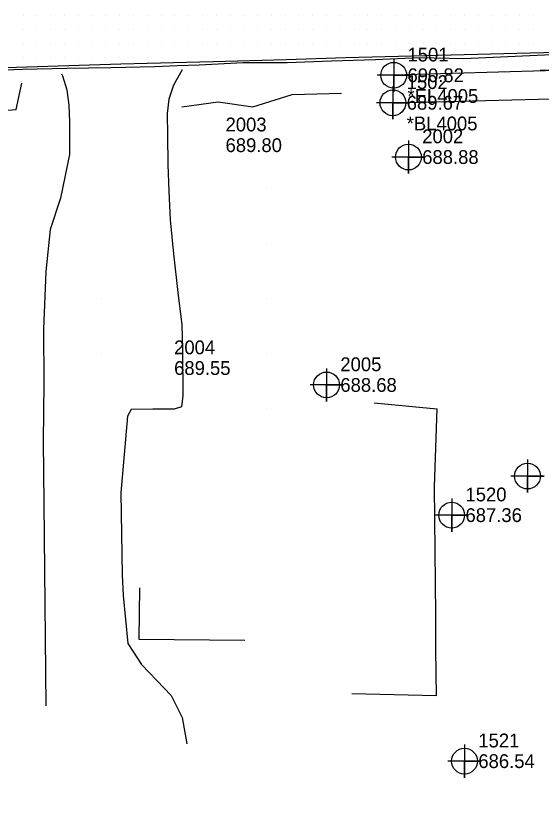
# Model space of a CAD drawing. Extents: x 1755643 to 1760494, y 736519 to 737621.
# Drawn here: x 1757879.9 to 1757975.2, y 736844.1 to 736986.2 of the extents above; entities that cross this region are included whole.
import ezdxf

# ---------------------------------------------------------------- set-up
doc = ezdxf.new("R2010")
doc.units = 0
for name, color, linetype in [('Exist Horizontal Alignment Curve and Spiral Data', 7, 'Continuous'), ('Exist Horizontal Alignment Direction Label', 7, 'Continuous'), ('Exist Railroads Standard Gauge', 7, 'Continuous'), ('Exist Roads EOT', 7, 'Continuous'), ('Old_Level_3', 7, 'Continuous'), ('Prop Corridor Linear Feature', 7, 'Continuous'), ('Prop EOT Dash', 7, 'Continuous'), ('Prop Lane Lines', 7, 'Continuous'), ('Prop Paint Stripe', 7, 'Continuous'), ('Prop Paved Shoulder', 7, 'Continuous'), ('Scratch_Level_1', 7, 'Continuous'), ('Scratch_Level_2', 7, 'Continuous'), ('Scratch_Level_5', 7, 'Continuous'), ('Scratch_Level_9', 7, 'Continuous')]:
    doc.layers.add(name, color=color, linetype=linetype)

msp = doc.modelspace()

# ---------------------------------------------------------------- linework, layer by layer
at = {"layer": 'Exist Horizontal Alignment Curve and Spiral Data'}
for points in [[(1757951.09, 736963.61), (1757951.09, 736957.61), (1757951.09, 736960.61), (1757954.09, 736960.61), (1757948.09, 736960.61)], [(1757936.25, 736922.27), (1757936.25, 736916.27), (1757936.25, 736919.27), (1757939.25, 736919.27), (1757933.25, 736919.27)], [(1757972.67, 736905.75), (1757972.67, 736899.75), (1757972.67, 736902.75), (1757975.67, 736902.75), (1757969.67, 736902.75)], [(1757958.93, 736898.66), (1757958.93, 736892.66), (1757958.93, 736895.66), (1757961.93, 736895.66), (1757955.93, 736895.66)], [(1757961.26, 736854.04), (1757961.26, 736848.04), (1757961.26, 736851.04), (1757964.26, 736851.04), (1757958.26, 736851.04)]]:
    msp.add_lwpolyline(points, dxfattribs=at)
for centre in [(1757951.09, 736960.61), (1757936.25, 736919.27), (1757972.67, 736902.75), (1757958.93, 736895.66), (1757961.26, 736851.04)]:
    msp.add_circle(centre, 2.34, dxfattribs=at)
at = {"layer": 'Exist Railroads Standard Gauge'}
for points in [[(1757888.22, 736975.69), (1757888.36, 736975.33), (1757889.19, 736972.8), (1757889.53, 736969.99), (1757889.65, 736966.99), (1757889.68, 736961.07), (1757888.01, 736953.18), (1757886.14, 736947.49), (1757885.38, 736939.87), (1757884.94, 736929.36), (1757884.98, 736919.6), (1757884.89, 736909.08), (1757884.99, 736897.85), (1757885.16, 736879.5), (1757885.39, 736861.05)], [(1757910.1, 736976.44), (1757908.52, 736973.63), (1757907.65, 736971.11), (1757907.38, 736968.52), (1757907.41, 736964.52), (1757907.5, 736959.27), (1757907.69, 736954.39), (1757907.92, 736949.25), (1757908.49, 736943.06), (1757909.29, 736936.07), (1757910.03, 736930.15), (1757910.12, 736925.65), (1757910.18, 736917.37), (1757909.95, 736915.28), (1757908.61, 736914.91), (1757904.76, 736914.88), (1757900.84, 736914.84), (1757900.16, 736913.63), (1757898.97, 736899.73), (1757899.21, 736884.83), (1757899.36, 736881.07), (1757900.24, 736872.37), (1757902.71, 736868.56), (1757905.48, 736865.69), (1757908.09, 736862.97), (1757910.08, 736858.98), (1757910.94, 736854.21)], [(1757876.09, 736968.9), (1757879.99, 736969.25), (1757881.01, 736973.98)], [(1757910.02, 736969.73), (1757916.63, 736970.65), (1757922.89, 736969.7), (1757930.01, 736971.93), (1757938.97, 736972.17)], [(1757944.85, 736916), (1757956.24, 736914.95), (1757955.76, 736900.8), (1757955.97, 736877.58), (1757956.02, 736871.3), (1757956.1, 736862.88), (1757940.85, 736863.23)], [(1757902.32, 736882.45), (1757902.22, 736873.18), (1757921.41, 736872.97)]]:
    msp.add_lwpolyline(points, dxfattribs=at)
at = {"layer": 'Prop Corridor Linear Feature'}
msp.add_lwpolyline([(1757909.25, 736977.13), (1757905.15, 736976.98), (1757897.16, 736976.76), (1757889.16, 736976.64)], dxfattribs=at)
at = {"layer": 'Prop Lane Lines'}
for points in [[(1757977.96, 736979.28), (1757977.96, 736973.28), (1757977.96, 736976.28), (1757980.96, 736976.28), (1757974.96, 736976.28)], [(1757948.42, 736978.44), (1757948.42, 736972.44), (1757948.42, 736975.44), (1757951.42, 736975.44), (1757945.42, 736975.44)], [(1757948.28, 736973.45), (1757948.28, 736967.45), (1757948.28, 736970.45), (1757951.28, 736970.45), (1757945.28, 736970.45)]]:
    msp.add_lwpolyline(points, dxfattribs=at)
for centre in [(1757948.42, 736975.44), (1757948.28, 736970.45)]:
    msp.add_circle(centre, 2.34, dxfattribs=at)
at = {"layer": 'Prop Paint Stripe'}
for p, q in [((1757925.38, 736954.98), (1757925.38, 736954.98)), ((1757925.38, 736944.98), (1757925.38, 736944.98)), ((1757895.38, 736934.98), (1757895.38, 736934.98)), ((1757925.38, 736934.98), (1757925.38, 736934.98)), ((1757895.38, 736924.97), (1757895.38, 736924.97)), ((1757925.38, 736924.97), (1757925.38, 736924.97)), ((1757925.38, 736914.97), (1757925.38, 736914.97))]:
    msp.add_line(p, q, dxfattribs=at)
at = {"layer": 'Scratch_Level_1'}
for points in [[(1758035.13, 736980.14), (1758033.1, 736980.09), (1758025.11, 736979.84), (1758017.1, 736979.8), (1758009.11, 736979.67), (1758001.11, 736979.56), (1757993.11, 736979.26), (1757985.11, 736979.44), (1757977.11, 736979.13), (1757969.12, 736978.8), (1757961.13, 736978.43), (1757953.12, 736978.6), (1757945.13, 736978.24), (1757937.13, 736977.97), (1757929.14, 736977.68), (1757921.13, 736977.68), (1757913.14, 736977.27), (1757909.25, 736977.13)], [(1757889.16, 736976.64), (1757881.16, 736976.48), (1757873.16, 736976.2), (1757865.11, 736976.03)]]:
    msp.add_lwpolyline(points, dxfattribs=at)
at = {"layer": 'Scratch_Level_2'}
for p, q in [((1757881.25, 736986.25), (1757881.25, 736986.25)), ((1757883.75, 736986.25), (1757883.75, 736986.25)), ((1757886.25, 736986.25), (1757886.25, 736986.25)), ((1757888.75, 736986.25), (1757888.75, 736986.25)), ((1757891.25, 736986.25), (1757891.25, 736986.25)), ((1757893.75, 736986.25), (1757893.75, 736986.25)), ((1757896.25, 736986.25), (1757896.25, 736986.25)), ((1757898.75, 736986.25), (1757898.75, 736986.25)), ((1757901.25, 736986.25), (1757901.25, 736986.25)), ((1757903.75, 736986.25), (1757903.75, 736986.25)), ((1757906.25, 736986.25), (1757906.25, 736986.25)), ((1757908.75, 736986.25), (1757908.75, 736986.25)), ((1757911.25, 736986.25), (1757911.25, 736986.25)), ((1757913.75, 736986.25), (1757913.75, 736986.25)), ((1757916.25, 736986.25), (1757916.25, 736986.25)), ((1757918.75, 736986.25), (1757918.75, 736986.25)), ((1757921.25, 736986.25), (1757921.25, 736986.25)), ((1757923.75, 736986.25), (1757923.75, 736986.25)), ((1757926.25, 736986.25), (1757926.25, 736986.25)), ((1757928.75, 736986.25), (1757928.75, 736986.25)), ((1757931.25, 736986.25), (1757931.25, 736986.25)), ((1757933.75, 736986.25), (1757933.75, 736986.25)), ((1757936.25, 736986.25), (1757936.25, 736986.25)), ((1757938.75, 736986.25), (1757938.75, 736986.25)), ((1757941.25, 736986.25), (1757941.25, 736986.25)), ((1757943.75, 736986.25), (1757943.75, 736986.25)), ((1757946.25, 736986.25), (1757946.25, 736986.25)), ((1757948.75, 736986.25), (1757948.75, 736986.25)), ((1757951.25, 736986.25), (1757951.25, 736986.25)), ((1757953.75, 736986.25), (1757953.75, 736986.25)), ((1757956.25, 736986.25), (1757956.25, 736986.25)), ((1757958.75, 736986.25), (1757958.75, 736986.25)), ((1757961.25, 736986.25), (1757961.25, 736986.25)), ((1757963.75, 736986.25), (1757963.75, 736986.25)), ((1757966.25, 736986.25), (1757966.25, 736986.25)), ((1757968.75, 736986.25), (1757968.75, 736986.25)), ((1757971.25, 736986.25), (1757971.25, 736986.25)), ((1757973.75, 736986.25), (1757973.75, 736986.25)), ((1757881.25, 736983.75), (1757881.25, 736983.75)), ((1757883.75, 736983.75), (1757883.75, 736983.75)), ((1757886.25, 736983.75), (1757886.25, 736983.75)), ((1757888.75, 736983.75), (1757888.75, 736983.75)), ((1757891.25, 736983.75), (1757891.25, 736983.75)), ((1757893.75, 736983.75), (1757893.75, 736983.75)), ((1757896.25, 736983.75), (1757896.25, 736983.75)), ((1757898.75, 736983.75), (1757898.75, 736983.75)), ((1757901.25, 736983.75), (1757901.25, 736983.75)), ((1757903.75, 736983.75), (1757903.75, 736983.75)), ((1757906.25, 736983.75), (1757906.25, 736983.75)), ((1757908.75, 736983.75), (1757908.75, 736983.75)), ((1757911.25, 736983.75), (1757911.25, 736983.75)), ((1757913.75, 736983.75), (1757913.75, 736983.75)), ((1757916.25, 736983.75), (1757916.25, 736983.75)), ((1757918.75, 736983.75), (1757918.75, 736983.75)), ((1757921.25, 736983.75), (1757921.25, 736983.75)), ((1757923.75, 736983.75), (1757923.75, 736983.75)), ((1757926.25, 736983.75), (1757926.25, 736983.75)), ((1757928.75, 736983.75), (1757928.75, 736983.75)), ((1757931.25, 736983.75), (1757931.25, 736983.75)), ((1757933.75, 736983.75), (1757933.75, 736983.75)), ((1757936.25, 736983.75), (1757936.25, 736983.75)), ((1757938.75, 736983.75), (1757938.75, 736983.75)), ((1757941.25, 736983.75), (1757941.25, 736983.75)), ((1757943.75, 736983.75), (1757943.75, 736983.75)), ((1757946.25, 736983.75), (1757946.25, 736983.75)), ((1757948.75, 736983.75), (1757948.75, 736983.75)), ((1757951.25, 736983.75), (1757951.25, 736983.75)), ((1757953.75, 736983.75), (1757953.75, 736983.75)), ((1757956.25, 736983.75), (1757956.25, 736983.75)), ((1757958.75, 736983.75), (1757958.75, 736983.75)), ((1757961.25, 736983.75), (1757961.25, 736983.75)), ((1757963.75, 736983.75), (1757963.75, 736983.75)), ((1757966.25, 736983.75), (1757966.25, 736983.75)), ((1757968.75, 736983.75), (1757968.75, 736983.75)), ((1757971.25, 736983.75), (1757971.25, 736983.75)), ((1757973.75, 736983.75), (1757973.75, 736983.75)), ((1757881.25, 736981.25), (1757881.25, 736981.25)), ((1757883.75, 736981.25), (1757883.75, 736981.25)), ((1757886.25, 736981.25), (1757886.25, 736981.25)), ((1757888.75, 736981.25), (1757888.75, 736981.25)), ((1757891.25, 736981.25), (1757891.25, 736981.25)), ((1757893.75, 736981.25), (1757893.75, 736981.25)), ((1757896.25, 736981.25), (1757896.25, 736981.25)), ((1757898.75, 736981.25), (1757898.75, 736981.25)), ((1757901.25, 736981.25), (1757901.25, 736981.25)), ((1757903.75, 736981.25), (1757903.75, 736981.25)), ((1757906.25, 736981.25), (1757906.25, 736981.25)), ((1757908.75, 736981.25), (1757908.75, 736981.25)), ((1757911.25, 736981.25), (1757911.25, 736981.25)), ((1757913.75, 736981.25), (1757913.75, 736981.25)), ((1757916.25, 736981.25), (1757916.25, 736981.25)), ((1757918.75, 736981.25), (1757918.75, 736981.25)), ((1757921.25, 736981.25), (1757921.25, 736981.25)), ((1757923.75, 736981.25), (1757923.75, 736981.25)), ((1757926.25, 736981.25), (1757926.25, 736981.25)), ((1757928.75, 736981.25), (1757928.75, 736981.25)), ((1757931.25, 736981.25), (1757931.25, 736981.25)), ((1757933.75, 736981.25), (1757933.75, 736981.25)), ((1757936.25, 736981.25), (1757936.25, 736981.25)), ((1757938.75, 736981.25), (1757938.75, 736981.25)), ((1757941.25, 736981.25), (1757941.25, 736981.25)), ((1757943.75, 736981.25), (1757943.75, 736981.25)), ((1757946.25, 736981.25), (1757946.25, 736981.25)), ((1757948.75, 736981.25), (1757948.75, 736981.25)), ((1757951.25, 736981.25), (1757951.25, 736981.25)), ((1757953.75, 736981.25), (1757953.75, 736981.25)), ((1757956.25, 736981.25), (1757956.25, 736981.25)), ((1757958.75, 736981.25), (1757958.75, 736981.25)), ((1757961.25, 736981.25), (1757961.25, 736981.25)), ((1757963.75, 736981.25), (1757963.75, 736981.25)), ((1757966.25, 736981.25), (1757966.25, 736981.25)), ((1757968.75, 736981.25), (1757968.75, 736981.25)), ((1757971.25, 736981.25), (1757971.25, 736981.25)), ((1757973.75, 736981.25), (1757973.75, 736981.25)), ((1757881.25, 736978.75), (1757881.25, 736978.75)), ((1757883.75, 736978.75), (1757883.75, 736978.75)), ((1757886.25, 736978.75), (1757886.25, 736978.75)), ((1757888.75, 736978.75), (1757888.75, 736978.75)), ((1757891.25, 736978.75), (1757891.25, 736978.75)), ((1757893.75, 736978.75), (1757893.75, 736978.75)), ((1757896.25, 736978.75), (1757896.25, 736978.75)), ((1757898.75, 736978.75), (1757898.75, 736978.75)), ((1757901.25, 736978.75), (1757901.25, 736978.75)), ((1757903.75, 736978.75), (1757903.75, 736978.75)), ((1757906.25, 736978.75), (1757906.25, 736978.75)), ((1757908.75, 736978.75), (1757908.75, 736978.75)), ((1757911.25, 736978.75), (1757911.25, 736978.75)), ((1757913.75, 736978.75), (1757913.75, 736978.75)), ((1757916.25, 736978.75), (1757916.25, 736978.75)), ((1757918.75, 736978.75), (1757918.75, 736978.75)), ((1757921.25, 736978.75), (1757921.25, 736978.75)), ((1757923.75, 736978.75), (1757923.75, 736978.75)), ((1757926.25, 736978.75), (1757926.25, 736978.75))]:
    msp.add_line(p, q, dxfattribs=at)
at = {"layer": 'Scratch_Level_5'}
msp.add_lwpolyline([(1758065.76, 736981.72), (1758038.13, 736981.07), (1758029.23, 736980.82), (1758020.64, 736980.63), (1757997.71, 736980.08), (1757970.76, 736979.41), (1757939.72, 736978.58), (1757928.95, 736978.26), (1757915.67, 736977.88), (1757898.95, 736977.48), (1757878.16, 736976.8), (1757865.1, 736976.45)], dxfattribs=at)
at = {"layer": 'Scratch_Level_9'}
for points in [[(1758044.7, 736961.62), (1758042.55, 736976.67), (1758036.28, 736978.63), (1758011.71, 736977.15), (1757977.96, 736976.28), (1757948.42, 736975.44)], [(1757948.28, 736970.45), (1757979.41, 736971.2), (1757997.7, 736970.69), (1757996.98, 736960.28), (1758000.48, 736938.14), (1758002.68, 736915.64), (1758001.11, 736895.52), (1757997.99, 736869.32), (1757996.7, 736844.11)]]:
    msp.add_lwpolyline(points, dxfattribs=at)

# ---------------------------------------------------------------- texts
at = {"layer": 'Exist Horizontal Alignment Direction Label'}
for s, p in [('*EL4005', (1757950.92, 736970.44)), ('*BL4005', (1757950.78, 736965.45))]:
    msp.add_text(s, height=2.5, dxfattribs=at).set_placement(p)
at = {"layer": 'Exist Roads EOT'}
for s, p in [('2003', (1757917.94, 736965.26)), ('2002', (1757953.59, 736963.11)), ('2004', (1757908.62, 736924.84)), ('2005', (1757938.75, 736921.77)), ('1520', (1757961.43, 736898.16)), ('1521', (1757963.76, 736853.54))]:
    msp.add_text(s, height=2.5, dxfattribs=at).set_placement(p)
at = {"layer": 'Old_Level_3'}
for s, p in [('690.82', (1757950.92, 736974.19)), ('689.67', (1757950.78, 736969.2))]:
    msp.add_text(s, height=2.5, dxfattribs=at).set_placement(p)
at = {"layer": 'Prop EOT Dash'}
for s, p in [('1501', (1757950.92, 736977.94)), ('1502', (1757950.78, 736972.95))]:
    msp.add_text(s, height=2.5, dxfattribs=at).set_placement(p)
at = {"layer": 'Prop Paved Shoulder'}
for s, p in [('689.80', (1757917.94, 736961.51)), ('688.88', (1757953.59, 736959.36)), ('689.55', (1757908.62, 736921.09)), ('688.68', (1757938.75, 736918.02)), ('687.36', (1757961.43, 736894.41)), ('686.54', (1757963.76, 736849.79))]:
    msp.add_text(s, height=2.5, dxfattribs=at).set_placement(p)

doc.saveas('drawing.dxf')
